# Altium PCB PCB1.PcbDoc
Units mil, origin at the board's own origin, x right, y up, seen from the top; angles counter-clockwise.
Board outline 1660 x 1905 mil, 2 copper layers (Top Layer, Bottom Layer); 10 components, 8 nets, 28 pads, 0 vias.
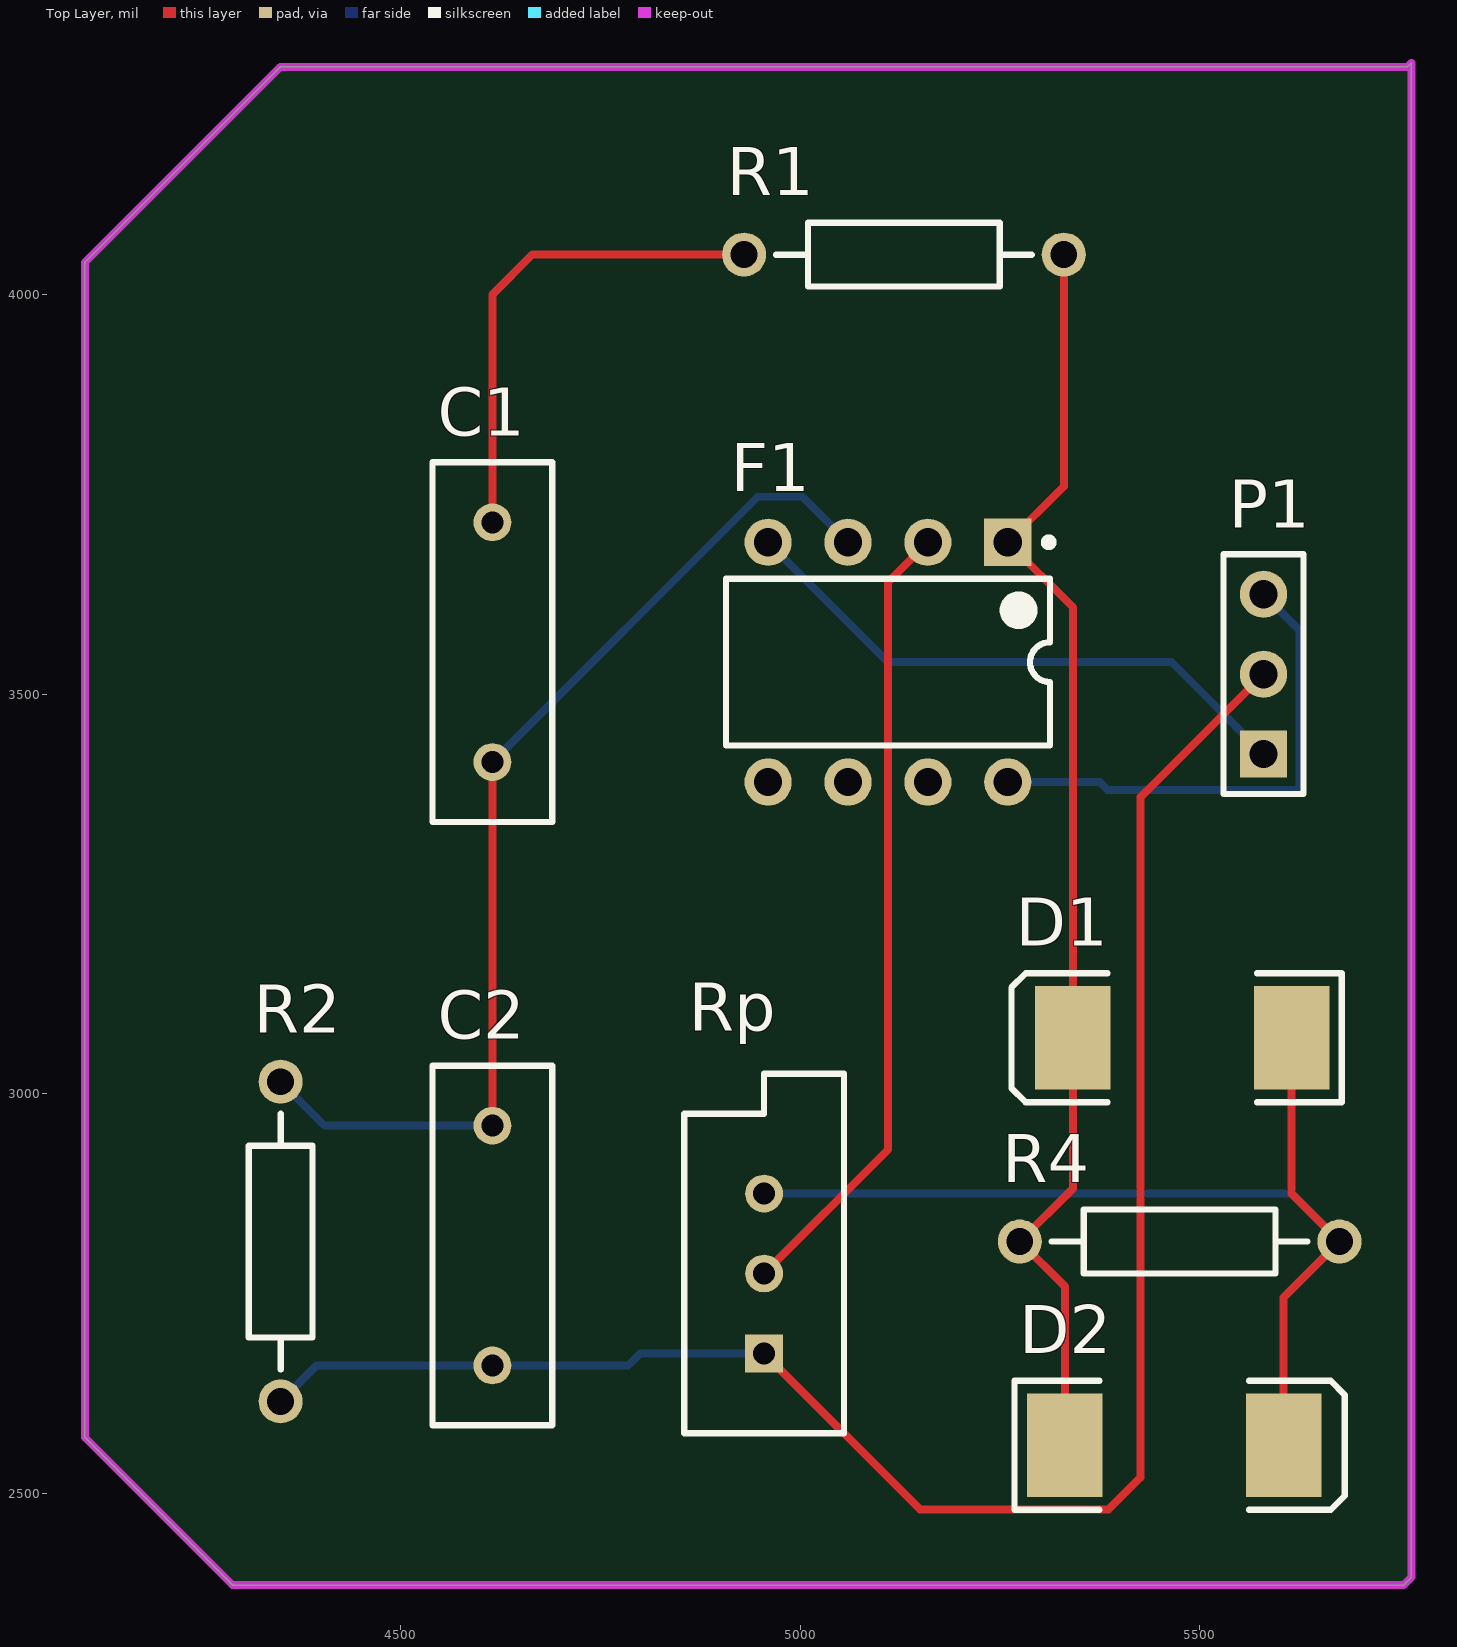
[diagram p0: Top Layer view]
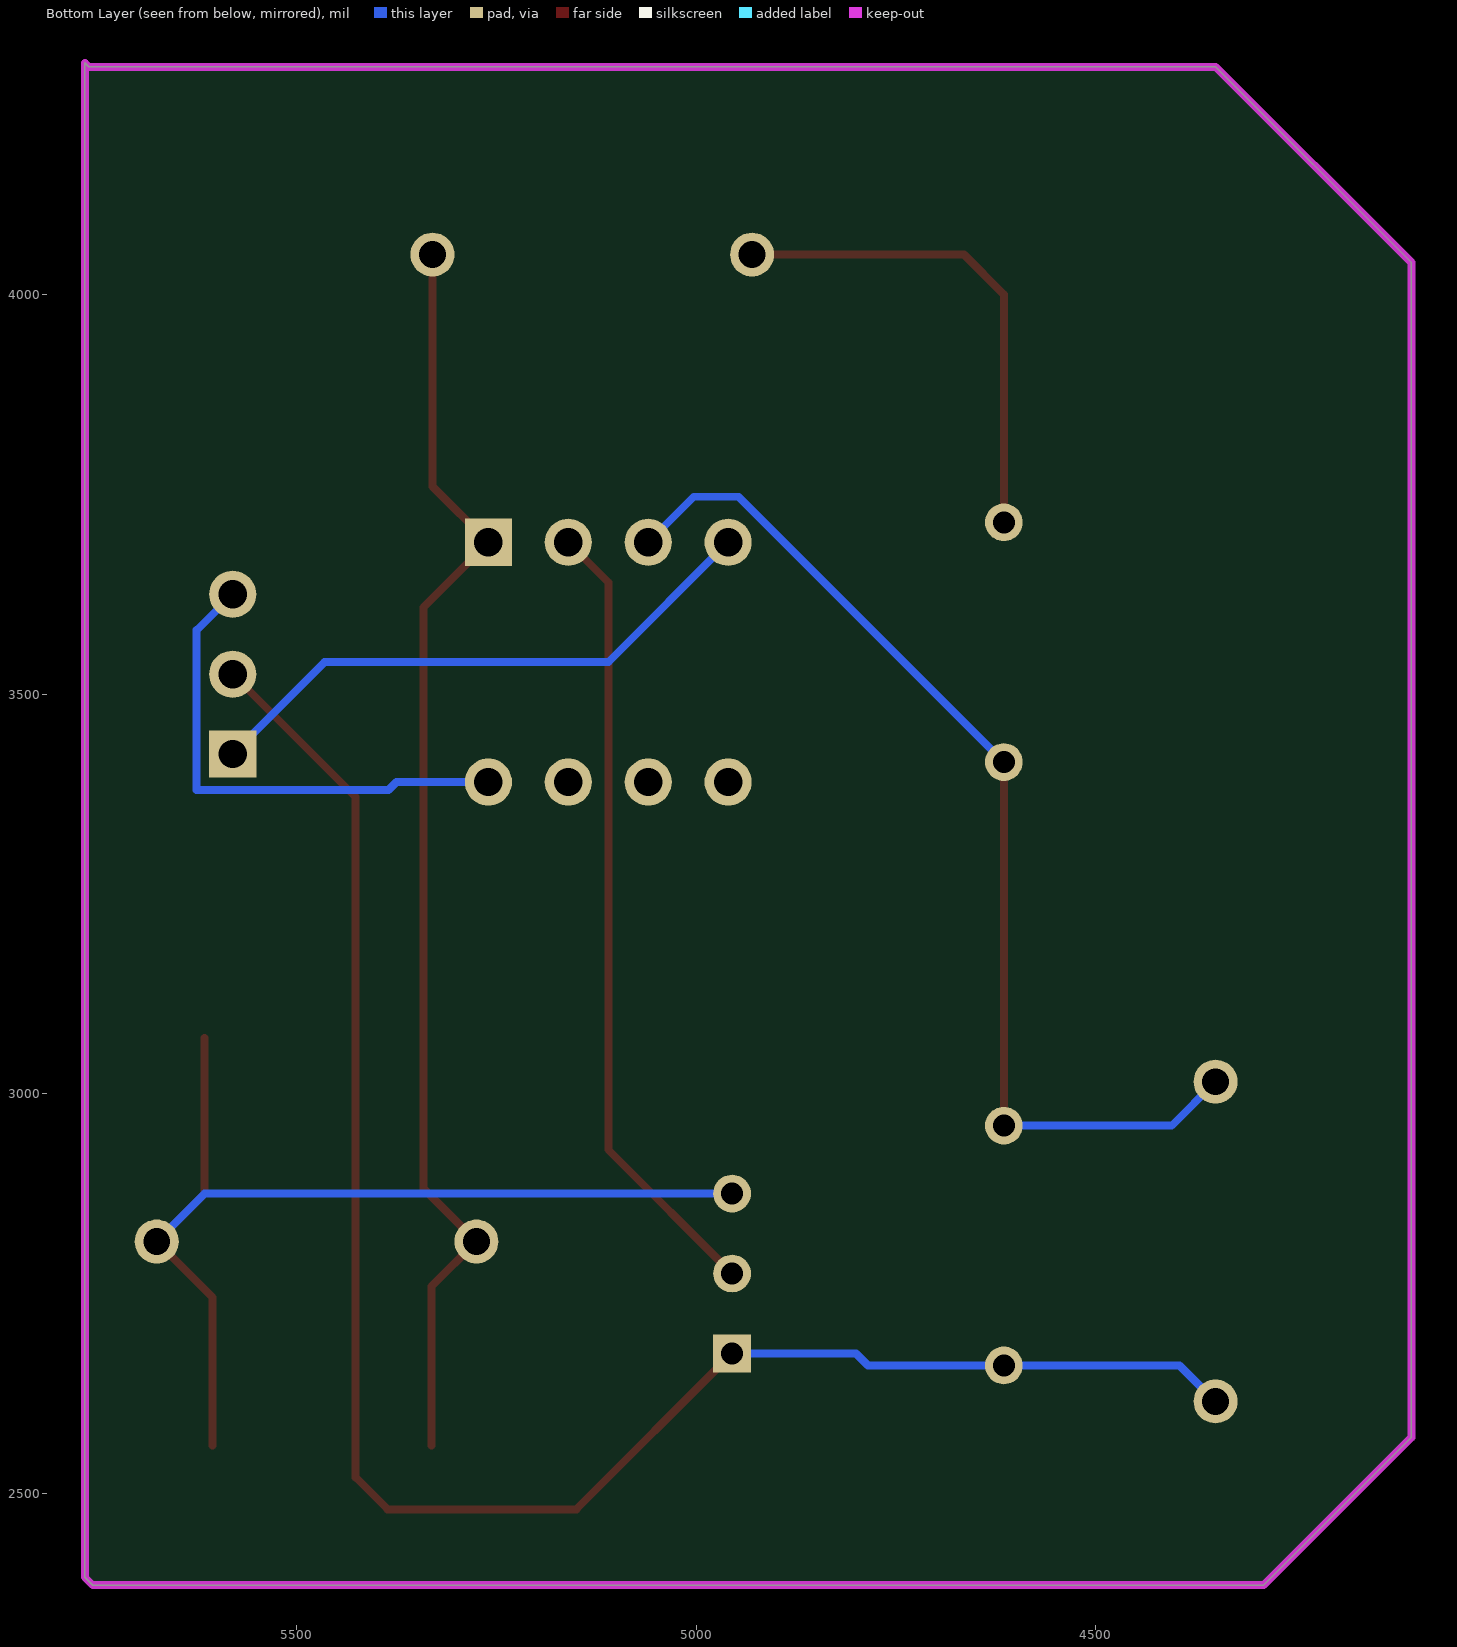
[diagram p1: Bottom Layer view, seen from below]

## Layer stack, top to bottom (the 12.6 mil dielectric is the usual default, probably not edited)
Top Solder: solder mask 0.4, Solder Resist, Dk 3.5
Top Layer: signal copper 1.4
Dielectric 1: dielectric 12.6, FR-4, Dk 4.8
Bottom Layer: signal copper 1.4
Bottom Solder: solder mask 0.4, Solder Resist, Dk 3.5

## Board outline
4105,2570 4290,2385 5755,2385 5765,2395 5765,4290 5760,4285 4350,4285 4105,4040

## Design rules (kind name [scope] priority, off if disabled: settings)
Clearance [All] p1: gap=10 ignorepadtopadclearanceinfootprint=FALSE except(0: Arc-Hole Track-Hole SMDPad-Hole THPad-Hole Via-Hole Fill-Hole Poly-Hole Region-Hole Text-Hole)
PolygonConnect [All] p1: connectstyle=Relief reliefconductorwidth=10 reliefentries=4 polygonreliefangle="90 Angle" airgapwidth=10
RoutingVias [All] p1: holewidth=28 width=50 viastyle="Through Hole" minholewidth=28 minwidth=50 maxholewidth=28 maxwidth=50
SolderMaskExpansion [All] p1: expansion=4 istentingtop=FALSE
Width [All] p1: maxlimit=10 minlimit=10 preferedwidth=10
30 further rules are at their usual default settings.

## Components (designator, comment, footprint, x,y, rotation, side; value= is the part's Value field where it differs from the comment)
C1 "Cap" RAD-0.3 4615,3565 r90 top value=100pF
C2 "Cap" RAD-0.3 4615,2810 r90 top value=10pF
D1 "Diode" SMC 5478.19,3070 r180 top
D2 "Diode" SMC 5468.19,2560 r0 top
F1 "1458" DIP-8 5110,3540 r270 top
P1 "Header 3" HDR1X3 5580,3425 r90 top
R1 "Res2" AXIAL-0.4 5130,4050 r0 top value=1K
R2 "Res2" AXIAL-0.4 4350,2815 r90 top value=1K
R4 "Res2" AXIAL-0.4 5475,2815 r180 top value=1K
Rp "RPot" VR5 4955,2775 r90 top value=1K

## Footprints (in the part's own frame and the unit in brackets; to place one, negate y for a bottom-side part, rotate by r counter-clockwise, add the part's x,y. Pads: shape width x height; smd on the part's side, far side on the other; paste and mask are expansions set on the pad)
AXIAL-0.4 [mm] "Axial Device, Thru-Hole; 2 Leads; 0.4 in Pin Spacing"
  round 1.4 hole 0.85: 1(-5.08,0) 2(5.08,0)
  silkscreen extent -4.06,-1.02 4.06,1.02
DIP-8 [mm] "DIP; 8 Leads; Row Spacing 7.62 mm; Pitch 2.54 mm"
  rect 1.5x1.5 hole 0.9: 1(-3.81,3.81)
  round 1.5 hole 0.9: 2(-3.81,1.27) 3(-3.81,-1.27) 4(-3.81,-3.81) 5(3.81,-3.81) 6(3.81,-1.27) 7(3.81,1.27) 8(3.81,3.81)
  silkscreen extent -3.93,-5.15 2.65,5.24, body extent -3.6,-5.15 3.6,5.15, height 5.08
HDR1X3 [mm] "Connector; Header; 3 Position"
  rect 1.5x1.5 hole 0.9: 1(0,0)
  round 1.5 hole 0.9: 2(2.54,0) 3(5.08,0)
  silkscreen extent -1.27,-1.27 6.35,1.27
RAD-0.3 [mm] "Radial Cap, Thru-Hole; 2 Leads; 0.3 in Pin Spacing"
  round 1.2 hole 0.7: 1(-3.81,0) 2(3.81,0)
  silkscreen extent -5.71,-1.91 5.71,1.91
SMC [mm] "DO-214-AB/SMC; 2 C-Bend Leads; Body 7.9 x 5.9 mm, inc. leads (LxW)"
  rect 2.4x3.3 smd: 1(-3.475,0) 2(3.475,0)
  silkscreen extent -5.07,-2.05 5.43,2.06
VR5 [mm] "Thru-Hole; 3 Leads"
  rect 1.2x1.2 hole 0.7: 1(-2.54,0)
  round 1.2 hole 0.7: 2(0,0) 3(2.54,0)
  silkscreen extent -5.08,-2.54 6.35,2.54

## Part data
C1 C2: "Capacitor"
D1 D2: "Default Diode"
P1: "Header, 3-Pin"
R1 R2 R4: "Resistor"
Rp: "Potentiometer"

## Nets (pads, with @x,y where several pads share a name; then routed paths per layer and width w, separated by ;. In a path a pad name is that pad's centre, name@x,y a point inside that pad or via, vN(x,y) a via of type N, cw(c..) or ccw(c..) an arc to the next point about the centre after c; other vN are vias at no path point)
+5V: F1.8 P1.3 | length 632.8
  Bottom Layer w10: F1.8 5375,3390 5385,3380 5625,3380 5625,3580 P1.3
-5V: F1.4 P1.1 | length 729.8
  Bottom Layer w10: F1.4 5110,3540 5465,3540 P1.1
GND: C2.1 P1.2 R2.1 Rp.1 | length 2267
  Top Layer w10: Rp.1 5150,2480 5386,2480 5426,2520 5426,3371 P1.2
  Bottom Layer w10: R2.1 4395,2660 C2.1 4785,2660 4800,2675 Rp.1
NetC1_1: C1.1 C2.2 F1.3 R2.2 | length 1348.9
  Top Layer w10: C2.2 C1.1
  Bottom Layer w10: R2.2 4405,2960 C2.2 ; C1.1 4947,3747 5003,3747 F1.3
NetC1_2: C1.2 R1.1 | length 620.7
  Top Layer w10: C1.2 4615,4000 4665,4050 R1.1
NetD1_1: D1.1 D2.2 R4.1 Rp.3 | length 1308.7
  Top Layer w10: D2.2 5605,2745 R4.1 5615,2875 D1.1
  Bottom Layer w10: Rp.3 5615,2875 R4.1
NetD1_2: D1.2 D2.1 F1.1 R1.2 R4.2 | length 1603.6
  Top Layer w10: R1.2 5330,3760 F1.1 5341.38,3608.62 D1.2 5341.38,2881.38 R4.2 5331.38,2758.62 D2.1
NetF1_2: F1.2 Rp.2 | length 999.9
  Top Layer w10: Rp.2 5110,2930 5110,3640 F1.2
pads on no net: F1.5 F1.6 F1.7

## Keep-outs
Keep-Out Layer:
  the board outline again, w10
